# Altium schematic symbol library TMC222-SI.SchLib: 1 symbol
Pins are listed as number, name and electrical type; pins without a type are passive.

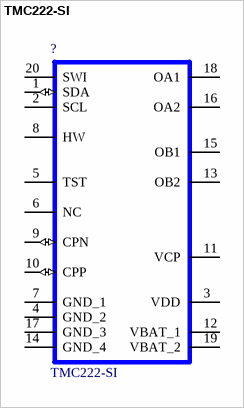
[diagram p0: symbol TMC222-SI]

## TMC222-SI
designator ?
Micro Stepping Stepper Motor Controller / Driver with Two Wire Serial Interface, SO20; Manufacturer: TRINAMIC; Geometry.Height: 2,65mm; Ordercode - Distri#1: 1460-1052-5-ND; Ordercode - Distri#2: 1214195
footprint TMC_SO20_SOT163-1_1.27_13X7.5
pins: 1 SDA (io), 2 SCL, 3 VDD (power), 4 GND_2, 5 TST, 6 NC, 7 GND_1, 8 HW, 9 CPN (io), 10 CPP (io), 11 VCP (power), 12 VBAT_1 (power), 13 OB2, 14 GND_4, 15 OB1, 16 OA2, 17 GND_3, 18 OA1, 19 VBAT_2 (power), 20 SWI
